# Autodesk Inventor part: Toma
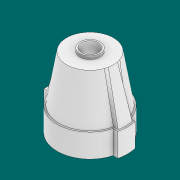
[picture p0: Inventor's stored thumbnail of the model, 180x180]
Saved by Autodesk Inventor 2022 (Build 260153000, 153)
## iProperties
Created: 2021-11
Part Number: Toma
Material: Generic
Document SubType Name: Modeling
Designer: santi
Density: 1 g/cm^3
Appearance: Default
Author: santi
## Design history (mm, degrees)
sketch "Sketch1"
  geometry: C1 r 21 at (0, 0); C2 r 20 at (0, 0); 1 further point
  constraints: 2 centre point, 1 coincident
  dimensions: "d0" = 42 diameter of C1; "d1" = 1 radial gap between concentric circles of C1 C2
extrude "Extrusion1" new body sketch "Sketch1" distance "d2" = 15; taper "d3" = 0 deg
sketch "Sketch2" dims "d4" = 48
  geometry: L1 (-24, 0)-(-24, 5.5); L2 (-24, 5.5)-(-24, -5.5); L3 (-24, -5.5)-(-20.267, -5.5); L4 (-24, 5.5)-(-20.267, 5.5); L5 (0, 0)-(0, 10.729); L6 (24, 0)-(24, 5.5); L7 (24, 5.5)-(24, -5.5); L8 (24, -5.5)-(20.267, -5.5); L9 (24, 5.5)-(20.267, 5.5); L10 (23, 5.5)-(23, -4.5); L11 (23, -4.5)-(20.267, -4.5); L12 (24, 4.5)-(20.267, 4.5); L13 (-23, 5.5)-(-23, -4.5); L14 (-23, -4.5)-(-20.267, -4.5); L15 (-24, 4.5)-(-20.267, 4.5); C1 r 21 at (0, 0) reference; C2 r 23 at (0, 0); C3 r 21 at (0, 0); C4 r 23 at (0, 0); A1 r 21 centre (0, 0) between (-20.267, -5.5) and (-20.267, 5.5) reference; A2 r 21 centre (0, 0) between (20.267, -5.5) and (20.267, 5.5); 16 further points
  constraints: 30 end point, 5 symmetric about line, 4 centre point, 4 point on circle, 4 vertical, 2 coincident, 2 parallel, 2 perpendicular, 2 point on line, 1 horizontal alignment, 10 other
  dimensions: "d5" = 1 dimension on C2; "d6" = 5.5 distance of L1.start L1.end; "d7" = 11 distance of L1.end L2.end; "d8" = 1 distance between parallel lines of L7 L10; "d9" = 1 distance between parallel lines of L9 L12; "d10" = 1 distance between parallel lines of L2 L13; "d11" = 1 distance between parallel lines of L4 L15
extrude "Extrusion2" join sketch "Sketch2" distance "d12" = 15; taper "d13" = 0 deg
sketch "Sketch3"
  geometry: L1 (-20.512, 4.5)-(20.512, 4.5); L2 (-20.512, -4.5)-(20.512, -4.5); A1 r 21 centre (0, 0) between (-20.512, 4.5) and (-20.512, -4.5) reference; A2 r 21 centre (0, 0) between (20.512, -4.5) and (20.512, 4.5) reference; A3 r 21 centre (0, 0) between (20.512, -4.5) and (20.512, 4.5) reference; 1 further point
  constraints: 4 end point, 2 horizontal
extrude "Extrusion3" cut sketch "Sketch3" distance "d14" = 15; taper "d15" = 0 deg
workplane "Work Plane1"
sketch "Sketch4"
  geometry: C1 r 15 at (0, 0); 1 further point
  constraints: 1 centre point, 1 coincident
  dimensions: "d17" = 30 diameter of C1
sketch "Sketch5"
  geometry: L1 (-24, -5.5)-(-20.267, -5.5) reference; L2 (-24, 5.5)-(-24, -5.5) reference; L3 (-20.267, 5.5)-(-24, 5.5) reference; L4 (23.361, 5.5)-(20.267, 5.5) reference; L5 (20.267, -5.5)-(23.361, -5.5) reference; A1 r 21 centre (0, 0) between (-20.267, -5.5) and (20.267, -5.5) reference; A2 r 21 centre (0, 0) between (20.267, 5.5) and (-20.267, 5.5) reference; A3 r 24 centre (0, 0) between (23.361, -5.5) and (23.361, 5.5) reference; 1 further point
loft "Loft1" dims "d18" = 0, "d19" = 90 deg, "d20" = 0, "d21" = 90 deg
  node "Edges1"
sketch "Sketch6"
  geometry: C1 r 6.5 at (0, 0); C2 r 5.5 at (0, 0); 1 further point
  constraints: 2 centre point, 1 coincident
  dimensions: "d22" = 13 diameter of C1; "d23" = 1 radial gap between concentric circles of C1 C2
extrude "Extrusion4" join sketch "Sketch6" distance "d24" = 2; taper "d25" = 0 deg
sketch "Sketch7"
  geometry: C1 r 5.5 at (0, 0) reference; 1 further point
extrude "Extrusion5" cut sketch "Sketch7" distance "d26" = 6; taper "d27" = 0 deg
sketch "Sketch8"
  geometry: L1 (-20.19, 4.5)-(-20.19, -5.5); L2 (-20.19, -5.5)-(-20.19, 14.5); C1 r 2.5 at (-20.19, 14.5); C2 r 2.5 at (-20.19, -5.5)
  constraints: 4 end point, 2 centre point, 2 coincident, 1 point on line, 1 vertical
  dimensions: "d28" = 10 distance of L1.start L1.end; "d29" = 20 distance of L1.end L2.end; "d30" = 5 diameter of C1; "d31" = 5 diameter of C2
extrude "Extrusion6" cut sketch "Sketch8" distance "d32" = 10; taper "d33" = 0 deg
body "Solid1"
node "Projected Loop1"
